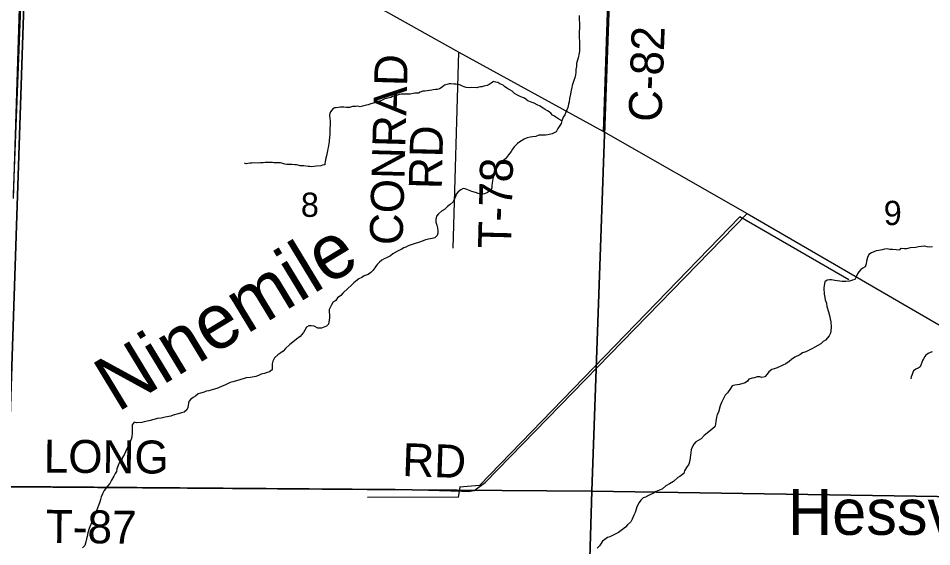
# Model space of a CAD drawing. Extents: x 1588073 to 2013523, y 1090242 to 1357120.
# Drawn here: x 1754621 to 1762930, y 1238801 to 1243614 of the extents above; entities that cross this region are included whole.
import ezdxf

# ---------------------------------------------------------------- set-up
doc = ezdxf.new("R2010")
doc.units = 0
for name, color, linetype in [('GM_X_County_Road', 7, 'Continuous'), ('GM_X_County_Road_Text', 7, 'Continuous'), ('GM_X_Minor_River', 7, 'Continuous'), ('GM_X_Minor_River_Text', 7, 'Continuous'), ('GM_X_Section', 7, 'Continuous'), ('GM_X_Section_Text', 7, 'Continuous'), ('GM_X_Township_Road', 7, 'Continuous'), ('GM_X_Township_Road_Text', 7, 'Continuous'), ('GM_X_Unincorporated_Text', 7, 'Continuous'), ('GM_X_US_Route', 7, 'Continuous')]:
    doc.layers.add(name, color=color, linetype=linetype)

msp = doc.modelspace()

# ---------------------------------------------------------------- linework, layer by layer
at = {"layer": 'GM_X_County_Road'}
msp.add_lwpolyline([(1759945.6, 1242581.8), (1760098.6, 1247214.7), (1760179.2, 1250093), (1760141.3, 1250222), (1760107.6, 1252739.2), (1760060.4, 1256704.3), (1760069.3, 1257059.2), (1760068.5, 1257195.5)], dxfattribs=at)
at = {"layer": 'GM_X_Minor_River'}
for p, q in [((1754681.7, 1245388.5), (1754574.9, 1241971)), ((1761186.1, 1241805.3), (1758815.1, 1239359.1)), ((1762176.8, 1241231.5), (1761184.1, 1241805.3)), ((1761184.1, 1241805.3), (1761186.1, 1241805.3)), ((1758636.6, 1239341.7), (1758621.2, 1239247.8)), ((1758815.1, 1239357.1), (1758634.6, 1239341.8)), ((1758634.6, 1239341.8), (1758636.6, 1239341.7)), ((1758815.1, 1239359.1), (1758815.1, 1239357.1)), ((1758621.3, 1239251.8), (1757796.3, 1239249.9)), ((1758621.2, 1239247.8), (1758621.3, 1239251.8))]:
    msp.add_line(p, q, dxfattribs=at)
for points in [[(1759722.6, 1243638.6), (1759724.2, 1243600.5), (1759725.8, 1243568.4), (1759724.5, 1243444.1), (1759726, 1243396), (1759725.7, 1243368), (1759727.5, 1243345.9), (1759725.2, 1243317.8), (1759723, 1243295.8), (1759712.6, 1243253.8), (1759700, 1243201.9), (1759697.7, 1243173.8)], [(1759697.7, 1243173.8), (1759693.4, 1243145.8), (1759693.2, 1243123.8), (1759690.9, 1243099.7), (1759682.6, 1243069.8), (1759674.4, 1243045.8), (1759659.9, 1243001.8), (1759655.7, 1242981.8), (1759647.3, 1242943.8), (1759645.1, 1242923.8), (1759636.7, 1242883.8), (1759632.4, 1242853.8), (1759626.1, 1242829.8), (1759619.8, 1242801.8), (1759611.6, 1242779.8), (1759601.3, 1242757.9), (1759593.1, 1242733.9), (1759578.9, 1242712), (1759566.5, 1242680.1), (1759558.2, 1242654.1), (1759529.7, 1242608.3), (1759513.4, 1242580.4), (1759477.2, 1242560.8), (1759439.1, 1242551.1), (1759417.1, 1242549.3), (1759383, 1242547.7), (1759357, 1242548), (1759328.9, 1242536.2), (1759298.8, 1242532.5), (1759278.8, 1242530.7), (1759250.7, 1242525), (1759222.5, 1242513.3), (1759182.2, 1242487.6), (1759162.1, 1242471.8), (1759131.8, 1242444.1), (1759115.5, 1242420.2), (1759103.3, 1242400.2), (1759080.9, 1242368.4), (1759052.6, 1242334.6), (1759012.2, 1242303), (1758992, 1242281.1), (1758973.7, 1242255.3), (1758965.5, 1242233.3), (1758957.2, 1242209.3), (1758944.9, 1242179.4), (1758936.6, 1242151.4), (1758932.2, 1242115.4), (1758929.9, 1242089.3), (1758927.7, 1242069.3), (1758919.5, 1242047.4), (1758889.3, 1242027.6), (1758863.1, 1242013.9), (1758841.1, 1242012.1), (1758805.1, 1242018.5), (1758779.2, 1242026.8), (1758747.3, 1242037.1), (1758717.4, 1242047.4), (1758687.5, 1242059.8), (1758667.5, 1242064), (1758645.4, 1242052.2), (1758621.1, 1242032.4), (1758604.9, 1242010.5), (1758598.7, 1241990.5), (1758590.4, 1241968.6), (1758578.2, 1241942.6), (1758549.9, 1241918.9), (1758525.7, 1241899.1), (1758497.4, 1241873.3), (1758471.2, 1241855.5), (1758443, 1241833.8), (1758424.7, 1241811.9), (1758418.4, 1241779.9), (1758420.1, 1241757.8), (1758429.9, 1241729.7), (1758435.6, 1241705.6), (1758437.3, 1241675.5), (1758437.1, 1241655.5), (1758430.9, 1241635.5), (1758410.6, 1241613.6), (1758386.6, 1241607.9), (1758366.5, 1241604.1), (1758324.4, 1241594.5), (1758304.3, 1241586.7), (1758260.1, 1241571.1), (1758232, 1241561.3), (1758167.7, 1241540), (1758147.6, 1241530.2), (1758127.5, 1241522.3), (1758103.3, 1241506.6), (1758077.2, 1241496.8), (1758026.9, 1241469.3), (1758006.7, 1241449.4), (1757976.5, 1241433.7), (1757950.3, 1241423.9), (1757928.2, 1241410.1), (1757908, 1241392.3), (1757885.8, 1241372.5), (1757871.5, 1241350.6), (1757849.2, 1241318.8), (1757826.9, 1241296.9), (1757802.7, 1241279.1)], [(1759566.7, 1242680.6), (1759539.4, 1242695.3), (1759511.6, 1242711.8), (1759497.8, 1242722), (1759481.9, 1242732.3), (1759464.2, 1242750.6), (1759450.3, 1242760.8), (1759434.4, 1242769.1), (1759414.5, 1242781.4), (1759396.7, 1242793.6), (1759380.8, 1242803.9), (1759367, 1242814.1), (1759341.1, 1242826.5), (1759313.3, 1242839), (1759287.4, 1242849.4), (1759257.6, 1242861.8), (1759239.7, 1242874.1), (1759225.8, 1242884.4), (1759207.9, 1242890.6), (1759180.1, 1242903.1), (1759156.2, 1242915.4), (1759136.4, 1242929.8), (1759112.7, 1242950.2), (1759092.8, 1242960.5), (1759065, 1242976.9), (1759045.3, 1242993.2), (1759031.4, 1243003.5), (1759015.5, 1243009.7), (1759001.5, 1243015.9), (1758983.7, 1243028.2), (1758963.7, 1243032.5), (1758943.8, 1243038.8), (1758921.5, 1243021.1), (1758905.4, 1243011.3), (1758887.2, 1243001.6), (1758857, 1242994), (1758839, 1242990.3), (1758824.9, 1242988.5), (1758810.9, 1242984.7), (1758792.8, 1242980.9), (1758746.7, 1242981.6), (1758728.7, 1242979.9), (1758696.7, 1242984.4), (1758676.8, 1242988.7), (1758660.8, 1242994.9), (1758643, 1243005.2), (1758627, 1243011.4), (1758601.1, 1243013.8), (1758583, 1243014.1), (1758557, 1243016.5), (1758541, 1243016.7), (1758518.9, 1243011), (1758498.8, 1243003.3), (1758476.5, 1242985.6), (1758452.3, 1242971.9), (1758430.1, 1242966.2), (1758416.1, 1242964.4), (1758396, 1242960.7), (1758382, 1242958.9), (1758361.9, 1242955.2), (1758341.8, 1242953.5), (1758319.8, 1242949.8), (1758301.7, 1242948.1), (1758277.6, 1242940.4), (1758261.4, 1242932.7), (1758245.4, 1242932.9), (1758227.4, 1242931.2), (1758213.3, 1242927.3), (1758187.2, 1242923.7), (1758157.2, 1242922.2), (1758143.2, 1242922.4), (1758103.1, 1242923), (1758087, 1242919.2), (1758060.9, 1242911.6), (1758046.8, 1242903.8), (1758024.7, 1242900.1), (1758010.6, 1242892.3), (1757982.4, 1242884.7), (1757968.4, 1242882.9), (1757954.3, 1242879.1), (1757926, 1242863.4), (1757897.9, 1242855.8), (1757879.7, 1242848.1), (1757861.7, 1242844.4), (1757841.5, 1242836.6), (1757827.5, 1242834.8), (1757803.3, 1242825.2), (1757785.2, 1242821.4), (1757765.1, 1242815.7), (1757751.1, 1242811.9), (1757731, 1242808.2), (1757711, 1242812.5), (1757693, 1242810.8), (1757677, 1242811), (1757660.9, 1242809.2), (1757632.8, 1242801.6), (1757618.7, 1242799.8), (1757604.7, 1242802.1), (1757582.8, 1242804.4), (1757566.7, 1242802.6), (1757550.7, 1242802.9)], [(1757550.7, 1242802.9), (1757534.6, 1242801.1), (1757512.6, 1242797.4), (1757498.6, 1242797.6), (1757484.5, 1242791.8), (1757460, 1242760.1), (1757455.7, 1242746.1), (1757453.5, 1242732.1), (1757455, 1242696.1), (1757456.8, 1242682), (1757458.5, 1242663.9), (1757458.1, 1242633.9), (1757455.8, 1242617.9), (1757455.6, 1242601.8), (1757454.9, 1242551.8), (1757452.6, 1242535.8), (1757452.4, 1242521.7), (1757450.2, 1242507.7), (1757447.9, 1242487.7), (1757445.7, 1242473.7), (1757441.2, 1242437.7), (1757436.9, 1242423.8), (1757432.7, 1242405.8), (1757424, 1242361.8), (1757419.7, 1242339.8), (1757415.4, 1242323.9), (1757411.2, 1242309.9), (1757409, 1242291.9), (1757408.7, 1242277.9), (1757388.7, 1242276.1), (1757372.6, 1242270.4), (1757334.5, 1242266.9), (1757286.4, 1242261.6), (1757272.4, 1242263.8), (1757258.4, 1242264), (1757218.4, 1242268.6), (1757202.4, 1242270.9), (1757186.4, 1242271.1), (1757166.4, 1242275.4), (1757150.4, 1242277.7), (1757136.5, 1242279.9), (1757108.4, 1242280.3), (1757076.4, 1242282.8), (1757062.4, 1242283), (1757044.4, 1242285.2), (1757028.5, 1242291.5), (1757006.5, 1242295.8), (1756992.6, 1242298), (1756974.5, 1242296.3), (1756946.5, 1242296.7), (1756932.5, 1242298.9), (1756904.5, 1242299.3), (1756866.4, 1242299.9), (1756848.4, 1242298.2), (1756824.3, 1242296.5), (1756806.3, 1242294.8), (1756758.3, 1242295.5), (1756744.2, 1242293.7), (1756726.2, 1242293.9), (1756708.1, 1242292.2), (1756694.1, 1242288.4), (1756680.2, 1242294.6)], [(1762638.8, 1241502.1), (1762574.5, 1241506.7), (1762548.5, 1241508.9), (1762524.5, 1241513.2), (1762500.5, 1241509.4), (1762478.4, 1241503.7), (1762448.3, 1241500), (1762424.3, 1241494.2), (1762382.1, 1241478.6), (1762357.9, 1241462.8), (1762347.6, 1241434.8), (1762337.3, 1241402.9), (1762333, 1241376.9), (1762324.7, 1241350.9), (1762304.6, 1241337.1), (1762284.4, 1241325.3), (1762268.2, 1241305.4), (1762256, 1241285.5), (1762243.7, 1241257.5), (1762229.5, 1241235.6), (1762209.4, 1241227.8), (1762183.2, 1241218.1), (1762149.2, 1241216.4), (1762115.2, 1241216.8), (1762049.2, 1241225.5), (1762019.3, 1241231.8), (1761999.2, 1241232), (1761979.2, 1241228.2), (1761957, 1241212.4), (1761950.7, 1241178.4), (1761950.4, 1241156.3), (1761951.9, 1241102.2), (1761959.5, 1241070), (1761961.3, 1241050), (1761973, 1241017.8), (1761974.7, 1240989.7), (1761992.2, 1240939.4), (1761999.9, 1240907.3), (1762005.6, 1240877.1), (1762011.3, 1240849), (1762014.8, 1240798.9), (1762012.4, 1240766.8), (1762008.2, 1240746.8), (1761996, 1240720.9), (1761963.5, 1240681.2), (1761943.4, 1240669.3), (1761921.2, 1240649.5), (1761866.8, 1240618), (1761846.7, 1240606.2), (1761786.3, 1240574.7), (1761754.2, 1240565.1), (1761730, 1240549.3), (1761683.7, 1240525.7), (1761653.5, 1240506), (1761633.3, 1240488.1), (1761603, 1240466.4), (1761576.9, 1240454.6), (1761524.6, 1240429.1), (1761496.5, 1240419.4), (1761474.4, 1240413.6), (1761448.2, 1240393.8), (1761433.9, 1240371.9), (1761411.7, 1240348.1), (1761385.6, 1240342.3), (1761365.6, 1240346.6), (1761343.6, 1240346.8), (1761319.5, 1240339), (1761295.5, 1240335.3), (1761267.4, 1240327.5), (1761253.1, 1240307.6), (1761233, 1240293.8), (1761180.8, 1240278.3), (1761138.7, 1240270.7), (1761114.6, 1240265), (1761100.4, 1240243.1), (1761071.9, 1240201.3), (1761051.7, 1240181.4), (1761043.5, 1240161.5), (1761019, 1240113.6), (1761006.6, 1240083.7), (1760992.1, 1240027.7), (1760977.8, 1240003.8), (1760971.6, 1239981.8), (1760967.1, 1239939.8), (1760964.9, 1239917.7), (1760956.6, 1239893.8), (1760920.3, 1239862.1), (1760888, 1239834.3), (1760861.8, 1239814.6), (1760833.4, 1239784.8), (1760807.2, 1239767), (1760783.1, 1239757.3), (1760766.9, 1239735.4), (1760752.6, 1239707.5), (1760742.3, 1239683.5), (1760738.1, 1239659.5), (1760735.8, 1239635.5), (1760733.6, 1239613.5), (1760731.3, 1239585.4), (1760720.9, 1239551.5), (1760698.6, 1239523.6)], [(1762638.2, 1241502.1), (1762653.8, 1241521.2), (1762683.8, 1241517), (1762703.8, 1241516.9), (1762735.9, 1241526.7), (1762786, 1241528.4), (1762810.1, 1241536.3), (1762866.1, 1241539.9), (1762886.1, 1241535.8), (1762908.1, 1241531.7), (1762936.2, 1241535.5)], [(1757802.7, 1241279.1), (1757766.6, 1241267.5), (1757746.4, 1241253.7), (1757720.3, 1241241.9), (1757673.9, 1241204.3), (1757647.6, 1241178.5), (1757621.3, 1241156.7), (1757572.8, 1241109.1), (1757556.6, 1241089.3), (1757524.4, 1241067.5), (1757508.1, 1241041.7), (1757481.9, 1241023.9), (1757469.7, 1241004), (1757449.2, 1240960.1), (1757448.9, 1240936), (1757452.7, 1240913.9), (1757452.4, 1240881.9), (1757446, 1240847.9), (1757443.8, 1240827.8), (1757423.6, 1240808), (1757379.4, 1240792.4), (1757345.4, 1240790.8), (1757311.5, 1240809.2), (1757285.6, 1240813.4), (1757265.5, 1240811.6), (1757243.4, 1240799.8), (1757229.1, 1240773.9), (1757214.9, 1240752), (1757184.5, 1240714.3), (1757152.2, 1240690.5), (1757117.9, 1240662.8), (1757091.6, 1240641.1), (1757053.2, 1240605.4), (1757029, 1240581.6), (1757008.8, 1240567.8), (1756980.6, 1240548), (1756950.3, 1240522.2), (1756936, 1240490.3), (1756931.7, 1240466.3), (1756931.2, 1240412.2), (1756907, 1240394.4), (1756884.9, 1240388.6), (1756860.8, 1240378.9), (1756830.7, 1240371.1), (1756806.5, 1240361.4), (1756780.4, 1240351.6), (1756734.3, 1240342.1), (1756694.2, 1240338.5), (1756626, 1240319.1), (1756571.7, 1240301.7), (1756549.7, 1240295.9), (1756529.6, 1240288.1), (1756505.4, 1240274.3), (1756469.3, 1240260.6), (1756447.1, 1240250.8), (1756427, 1240243), (1756394.9, 1240233.3), (1756352.8, 1240221.7), (1756330.7, 1240217.9), (1756310.6, 1240208.1), (1756278.5, 1240200.4), (1756256.4, 1240192.7), (1756232.2, 1240172.9), (1756212, 1240159), (1756189.8, 1240143.2), (1756173.6, 1240123.4), (1756165.3, 1240091.4), (1756163, 1240067.3), (1756154.8, 1240047.4), (1756130.6, 1240027.6), (1756104.5, 1240019.8), (1756074.4, 1240010.1), (1756030.2, 1239998.6), (1756008.1, 1239990.8), (1755958, 1239979.2), (1755919.9, 1239971.6), (1755885.8, 1239968), (1755865.7, 1239962.1), (1755807.6, 1239948.7), (1755767.4, 1239937.1), (1755743.3, 1239931.3), (1755697.3, 1239927.8), (1755675.3, 1239934.1), (1755657.1, 1239912.2), (1755656.2, 1239832), (1755654, 1239808), (1755649.8, 1239786), (1755625.2, 1239730.1), (1755608.8, 1239692.2), (1755596.5, 1239664.3), (1755584.2, 1239638.3), (1755565.9, 1239610.5), (1755563.7, 1239590.4), (1755539.4, 1239564.6), (1755529.1, 1239540.7), (1755518.8, 1239510.7), (1755514.6, 1239486.7), (1755502.4, 1239466.8), (1755490.1, 1239442.9), (1755467.7, 1239407), (1755453.4, 1239377.1)], [(1762935, 1240574.7), (1762915, 1240568.6), (1762897, 1240560.5), (1762877, 1240546.4), (1762867, 1240532.3), (1762855.1, 1240512.2), (1762847.1, 1240498.2), (1762839.2, 1240478.1), (1762831.2, 1240454), (1762825.3, 1240439.9), (1762807.3, 1240425.8), (1762787.3, 1240417.8), (1762763.3, 1240403.6), (1762757.4, 1240387.6), (1762751.4, 1240369.5), (1762743.5, 1240349.4), (1762739.5, 1240329.3)], [(1760698.6, 1239523.6), (1760680.3, 1239491.7), (1760676, 1239467.7), (1760639.7, 1239440), (1760619.6, 1239430.2), (1760581.2, 1239394.5), (1760545, 1239374.9), (1760512.8, 1239355.2), (1760480.5, 1239329.4), (1760454.3, 1239315.7), (1760424.2, 1239304), (1760398, 1239288.2), (1760353.7, 1239268.6), (1760327.5, 1239250.8), (1760305.5, 1239247.1), (1760285.3, 1239225.2), (1760269, 1239203.3), (1760248.6, 1239165.5), (1760240.4, 1239143.5), (1760232.1, 1239113.5), (1760219.8, 1239087.6), (1760205.4, 1239051.7), (1760193.1, 1239027.7), (1760162.8, 1239000), (1760144.6, 1238980.1), (1760116.3, 1238956.4), (1760080.1, 1238930.7), (1760027.7, 1238903.2), (1760003.6, 1238891.4), (1759979.5, 1238883.6), (1759957.3, 1238865.8), (1759935.1, 1238850), (1759918.9, 1238828.1), (1759906.7, 1238808.2), (1759888.4, 1238786.3)], [(1755453.4, 1239377.1), (1755433.1, 1239353.3), (1755402.7, 1239311.5), (1755386.4, 1239281.6), (1755376.1, 1239255.6), (1755367.8, 1239231.7), (1755363.6, 1239209.7), (1755351.2, 1239175.7), (1755341, 1239151.8), (1755322.5, 1239105.9), (1755310.2, 1239077.9), (1755295.8, 1239038), (1755285.6, 1239018.1), (1755265, 1238968.2), (1755252.6, 1238926.2), (1755248.2, 1238894.2), (1755242, 1238872.2), (1755235.7, 1238844.2), (1755225.4, 1238812.2), (1755205.1, 1238790.4)]]:
    msp.add_lwpolyline(points, dxfattribs=at)
at = {"layer": 'GM_X_Section'}
for points in [[(1749045.5, 1244692), (1754700.3, 1244653.1), (1754526.5, 1239347.7), (1748859.5, 1239350.7)], [(1754700.3, 1244653.1), (1760026.9, 1244607.2), (1759839.1, 1239305.9), (1754526.5, 1239347.7)], [(1760026.9, 1244607.2), (1765302.4, 1244480.3), (1765142.6, 1239224.6), (1759839.1, 1239305.9)], [(1754526.5, 1239347.7), (1759839.1, 1239305.9), (1759679.4, 1234018.4), (1754366.9, 1234062.3)], [(1759839.1, 1239305.9), (1765142.6, 1239224.6), (1764954.4, 1233927.1), (1759679.4, 1234018.4)]]:
    msp.add_lwpolyline(points, close=True, dxfattribs=at)
at = {"layer": 'GM_X_Township_Road'}
for points in [[(1754577.8, 1242010.1), (1754577.8, 1242010.1), (1754712.8, 1245495.6)], [(1758577.8, 1241520.8), (1758628.7, 1243303.4)], [(1758656.1, 1239306.6), (1758712.9, 1239304.8), (1758769.1, 1239311.9), (1758868.6, 1239386.5), (1761250, 1241834.4)], [(1754527.1, 1239352), (1758047.9, 1239325.8), (1758654.8, 1239306.6), (1758656.1, 1239306.6)]]:
    msp.add_lwpolyline(points, dxfattribs=at)
at = {"layer": 'GM_X_US_Route'}
msp.add_lwpolyline([(1749415, 1248436.4), (1751954.3, 1247015.3), (1754712.8, 1245495.6), (1756013.5, 1244772.3), (1758628.7, 1243303.4), (1759945.6, 1242581.8), (1761250, 1241834.4), (1763463.4, 1240552.9), (1763789.1, 1240364.4), (1764133.5, 1240165), (1764467.6, 1239971.6), (1764522, 1239940.1)], dxfattribs=at)

# ---------------------------------------------------------------- texts
at = {"layer": 'GM_X_County_Road_Text'}
msp.add_text('C-82', height=300, rotation=87.94216, dxfattribs=at).set_placement((1760471, 1242665.8))
at = {"layer": 'GM_X_Minor_River_Text'}
msp.add_text('Ninemile', height=500.3, rotation=31.22636, dxfattribs=at).set_placement((1755521.7, 1240020.2))
at = {"layer": 'GM_X_Section_Text'}
for s, p in [('8', (1757191.3, 1241804.9)), ('9', (1762493.3, 1241730.1))]:
    msp.add_text(s, height=221, rotation=0.00001, dxfattribs=at).set_placement(p)
at = {"layer": 'GM_X_Township_Road_Text'}
for s, rotation, p in [('CONRAD', 88.37234, (1758116.1, 1241544.2)), ('RD', 88.51931, (1758472.5, 1242054.6)), ('T-78', 88.58498, (1759102.2, 1241514.5)), ('LONG', 359.50421, (1754851.5, 1239476.2)), ('RD', 358.02611, (1758110.6, 1239445.3)), ('T-87', 359.29306, (1754870.5, 1238837.5))]:
    msp.add_text(s, height=300, rotation=rotation, dxfattribs=at).set_placement(p)
at = {"layer": 'GM_X_Unincorporated_Text'}
msp.add_text('Hessville', height=417, rotation=0.00001, dxfattribs=at).set_placement((1761622.1, 1238909.1))

doc.saveas('drawing.dxf')
